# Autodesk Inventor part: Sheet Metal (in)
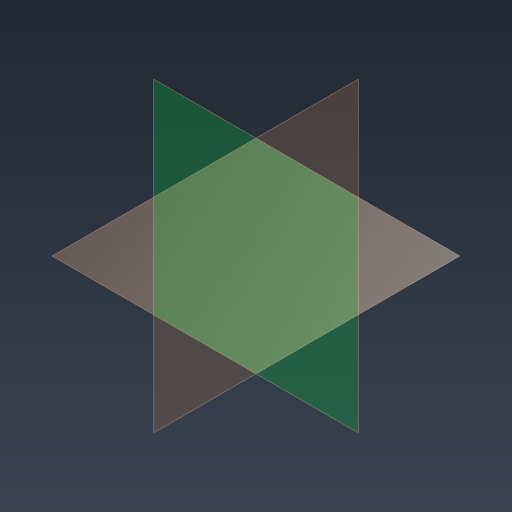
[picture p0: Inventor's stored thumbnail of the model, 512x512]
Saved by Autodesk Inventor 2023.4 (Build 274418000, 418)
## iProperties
Shininess: 64.0
Length Units: 11272
Angle Units: 11279
Time Units: 11290
Mass Units: 11286
Length Display Precision: 3
Angle Display Precision: 2
Compacted: True
Part Number: Sheet Metal (in)
Document SubType Name: Sheet Metal
Created: 2002-07
Material: Generic
Density: 1 g/cm^3
Sheet Metal Rule: Default
Appearance: Default
Density: 0.0
Volumn: 0.0
Area: 0.0
PropertySet Name: Model Information
Control State: 0
Master: False
Checked Out: False
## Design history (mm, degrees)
other parameters: "Thickness" = 3.048, "BendRadius" = 3.048 (= Thickness), "BendReliefWidth" = 3.048 (= Thickness), "BendReliefDepth" = 1.524 (= 0.5 x Thickness), "CornerReliefSize" = 12.192 (= 4 x Thickness), "SeamGap" = 0.00508, "MinimumRemnant" = 6.096 (= 2 x Thickness), "TransitionRadius" = 3.048 (= BendRadius), "JacobiRadiusSize" = 3.048 (= BendRadius), "GapSize" = 3.048 (= Thickness)
